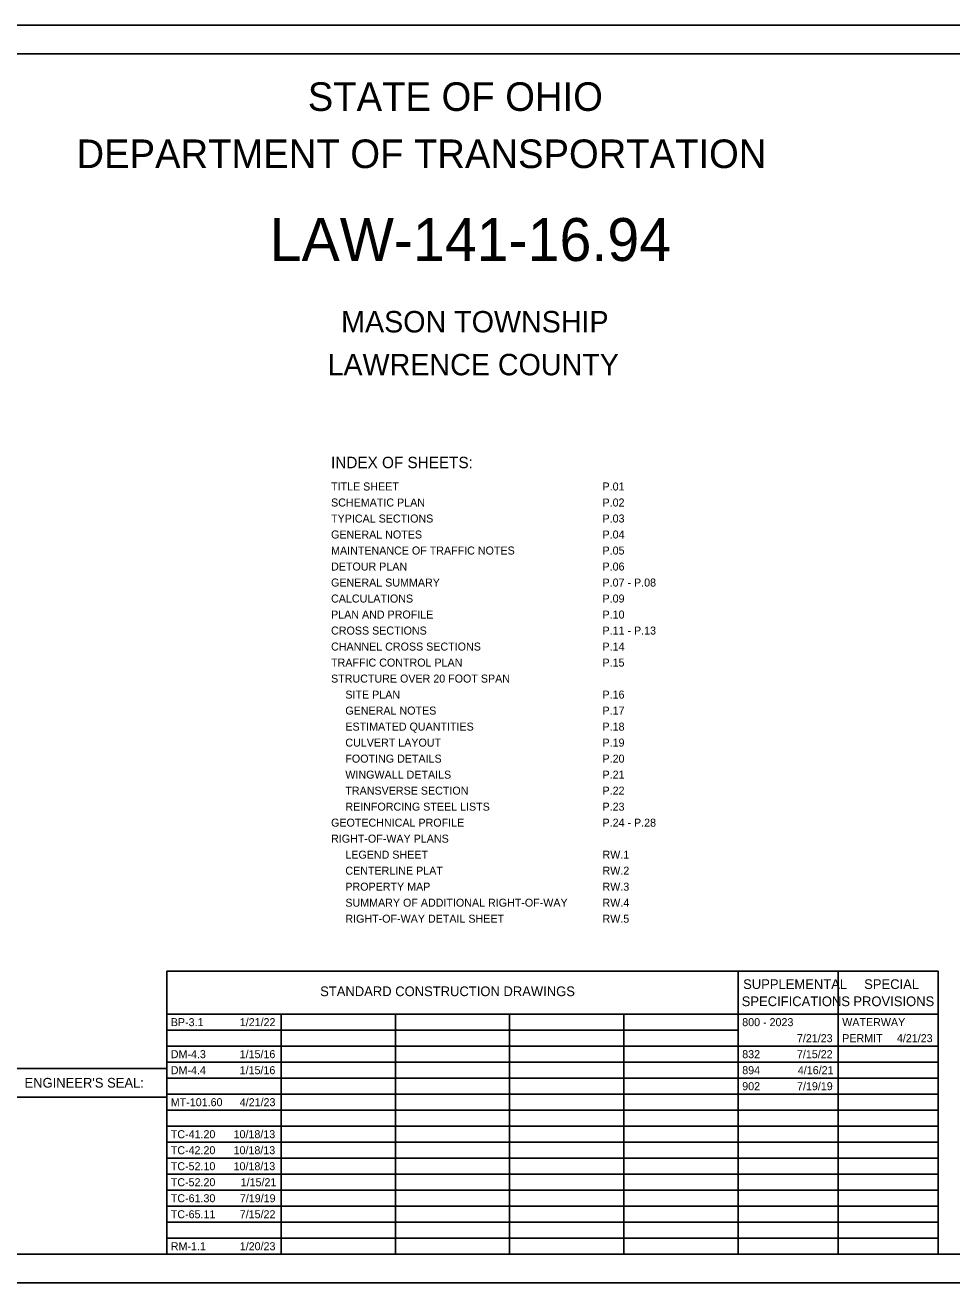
# Model space of a CAD drawing. Extents: x -6.4 to 34, y -1.2 to 22.
# Drawn here: x 9.02 to 25.24, y 0 to 22 of the extents above; entities that cross this region are included whole.
import ezdxf

# ---------------------------------------------------------------- set-up
doc = ezdxf.new("R2010")
doc.units = 0
for name, color, linetype in [('GM_X_County', 7, 'Continuous'), ('GM_X_Section', 7, 'Continuous'), ('GM_X_Township', 7, 'Continuous')]:
    doc.layers.add(name, color=color, linetype=linetype)

msp = doc.modelspace()

# ---------------------------------------------------------------- linework, layer by layer
at = {"layer": 'GM_X_County'}
msp.add_lwpolyline([(1.5, 21.5), (33.5, 21.5), (33.5, 0.5), (1.5, 0.5)], close=True, dxfattribs=at)
at = {"layer": 'GM_X_Section'}
msp.add_lwpolyline([(0, 0), (34, 0), (34, 22), (0, 22)], close=True, dxfattribs=at)
at = {"layer": 'GM_X_Township'}
for p, q in [((11.5, 0.5), (11.5, 5.45)), ((11.5, 5.45), (25, 5.45)), ((21.5, 0.5), (21.5, 5.45)), ((23.25, 0.5), (23.25, 5.45)), ((25, 0.5), (25, 5.45)), ((11.5, 4.7), (25, 4.7)), ((13.5, 0.5), (13.5, 4.7)), ((15.5, 0.5), (15.5, 4.7)), ((17.5, 0.5), (17.5, 4.7)), ((19.5, 0.5), (19.5, 4.7)), ((11.5, 4.42), (21.5, 4.42)), ((11.5, 4.14), (25, 4.14)), ((8.7, 3.75), (11.5, 3.75)), ((11.5, 3.86), (25, 3.86)), ((11.5, 3.58), (25, 3.58)), ((11.5, 3.3), (25, 3.3)), ((8.7, 3.25), (11.5, 3.25)), ((11.5, 3.02), (25, 3.02)), ((11.5, 2.74), (25, 2.74)), ((11.5, 2.46), (25, 2.46)), ((11.5, 2.18), (25, 2.18)), ((11.5, 1.9), (25, 1.9)), ((11.5, 1.62), (25, 1.62)), ((11.5, 1.34), (25, 1.34)), ((11.5, 1.06), (25, 1.06)), ((11.5, 0.78), (25, 0.78))]:
    msp.add_line(p, q, dxfattribs=at)

# ---------------------------------------------------------------- texts
for s, height, p in [('STATE OF OHIO', 0.5, (13.968, 20.5)), ('DEPARTMENT OF TRANSPORTATION', 0.5, (9.92, 19.5)), ('LAW-141-16.94', 0.75, (13.301, 17.875)), ('MASON TOWNSHIP', 0.375, (14.551, 16.625)), ('LAWRENCE COUNTY', 0.375, (14.313, 15.875)), ('INDEX OF SHEETS:', 0.2, (14.375, 14.25)), ('TITLE SHEET', 0.14, (14.375, 13.86)), ('P.01', 0.14, (19.125, 13.86)), ('SCHEMATIC PLAN', 0.14, (14.375, 13.58)), ('P.02', 0.14, (19.125, 13.58)), ('TYPICAL SECTIONS', 0.14, (14.375, 13.3)), ('P.03', 0.14, (19.125, 13.3)), ('GENERAL NOTES', 0.14, (14.375, 13.02)), ('P.04', 0.14, (19.125, 13.02)), ('MAINTENANCE OF TRAFFIC NOTES', 0.14, (14.375, 12.74)), ('P.05', 0.14, (19.125, 12.74)), ('DETOUR PLAN', 0.14, (14.375, 12.46)), ('P.06', 0.14, (19.125, 12.46)), ('GENERAL SUMMARY', 0.14, (14.375, 12.18)), ('P.07 - P.08', 0.14, (19.125, 12.18)), ('CALCULATIONS', 0.14, (14.375, 11.9)), ('P.09', 0.14, (19.125, 11.9)), ('PLAN AND PROFILE', 0.14, (14.375, 11.62)), ('P.10', 0.14, (19.125, 11.62)), ('CROSS SECTIONS', 0.14, (14.375, 11.34)), ('P.11 - P.13', 0.14, (19.125, 11.34)), ('CHANNEL CROSS SECTIONS', 0.14, (14.375, 11.06)), ('P.14', 0.14, (19.125, 11.06)), ('TRAFFIC CONTROL PLAN', 0.14, (14.375, 10.78)), ('P.15', 0.14, (19.125, 10.78)), ('STRUCTURE OVER 20 FOOT SPAN', 0.14, (14.375, 10.5)), ('SITE PLAN', 0.14, (14.625, 10.22)), ('P.16', 0.14, (19.125, 10.22)), ('GENERAL NOTES', 0.14, (14.625, 9.94)), ('P.17', 0.14, (19.125, 9.94)), ('ESTIMATED QUANTITIES', 0.14, (14.625, 9.66)), ('P.18', 0.14, (19.125, 9.66)), ('CULVERT LAYOUT', 0.14, (14.625, 9.38)), ('P.19', 0.14, (19.125, 9.38)), ('FOOTING DETAILS', 0.14, (14.625, 9.1)), ('P.20', 0.14, (19.125, 9.1)), ('WINGWALL DETAILS', 0.14, (14.625, 8.82)), ('P.21', 0.14, (19.125, 8.82)), ('TRANSVERSE SECTION', 0.14, (14.625, 8.54)), ('P.22', 0.14, (19.125, 8.54)), ('REINFORCING STEEL LISTS', 0.14, (14.625, 8.26)), ('P.23', 0.14, (19.125, 8.26)), ('GEOTECHNICAL PROFILE', 0.14, (14.375, 7.98)), ('P.24 - P.28', 0.14, (19.125, 7.98)), ('RIGHT-OF-WAY PLANS', 0.14, (14.375, 7.7)), ('LEGEND SHEET', 0.14, (14.625, 7.42)), ('RW.1', 0.14, (19.125, 7.42)), ('CENTERLINE PLAT', 0.14, (14.625, 7.14)), ('RW.2', 0.14, (19.125, 7.14)), ('PROPERTY MAP', 0.14, (14.625, 6.86)), ('RW.3', 0.14, (19.125, 6.86)), ('SUMMARY OF ADDITIONAL RIGHT-OF-WAY', 0.14, (14.625, 6.58)), ('RW.4', 0.14, (19.125, 6.58)), ('RIGHT-OF-WAY DETAIL SHEET', 0.14, (14.625, 6.3)), ('RW.5', 0.14, (19.125, 6.3)), ('SUPPLEMENTAL', 0.17, (21.586, 5.14)), ('SPECIAL', 0.17, (23.704, 5.14)), ('STANDARD CONSTRUCTION DRAWINGS', 0.17, (14.184, 5.015)), ('SPECIFICATIONS', 0.17, (21.561, 4.84)), ('PROVISIONS', 0.17, (23.515, 4.84)), ('BP-3.1', 0.14, (11.57, 4.49)), ('1/21/22', 0.14, (12.777, 4.49)), ('800 - 2023', 0.14, (21.57, 4.49)), ('WATERWAY', 0.14, (23.32, 4.49)), ('7/21/23', 0.14, (22.527, 4.21)), ('PERMIT', 0.14, (23.32, 4.21)), ('4/21/23', 0.14, (24.277, 4.21)), ('DM-4.3', 0.14, (11.57, 3.93)), ('1/15/16', 0.14, (12.775, 3.93)), ('832', 0.14, (21.57, 3.93)), ('7/15/22', 0.14, (22.527, 3.93)), ('DM-4.4', 0.14, (11.57, 3.65)), ('1/15/16', 0.14, (12.775, 3.65)), ('894', 0.14, (21.57, 3.65)), ('4/16/21', 0.14, (22.543, 3.65)), ("ENGINEER'S SEAL:", 0.17, (9.01, 3.415)), ('902', 0.14, (21.57, 3.37)), ('7/19/19', 0.14, (22.529, 3.37)), ('MT-101.60', 0.14, (11.57, 3.09)), ('4/21/23', 0.14, (12.777, 3.09)), ('TC-41.20', 0.14, (11.57, 2.53)), ('10/18/13', 0.14, (12.669, 2.53)), ('TC-42.20', 0.14, (11.57, 2.25)), ('10/18/13', 0.14, (12.669, 2.25)), ('TC-52.10', 0.14, (11.57, 1.97)), ('10/18/13', 0.14, (12.669, 1.97)), ('TC-52.20', 0.14, (11.57, 1.69)), ('1/15/21', 0.14, (12.793, 1.69)), ('TC-61.30', 0.14, (11.57, 1.41)), ('7/19/19', 0.14, (12.779, 1.41)), ('TC-65.11', 0.14, (11.57, 1.13)), ('7/15/22', 0.14, (12.777, 1.13)), ('RM-1.1', 0.14, (11.57, 0.57)), ('1/20/23', 0.14, (12.777, 0.57))]:
    msp.add_text(s, height=height, dxfattribs=at).set_placement(p)

doc.saveas('drawing.dxf')
